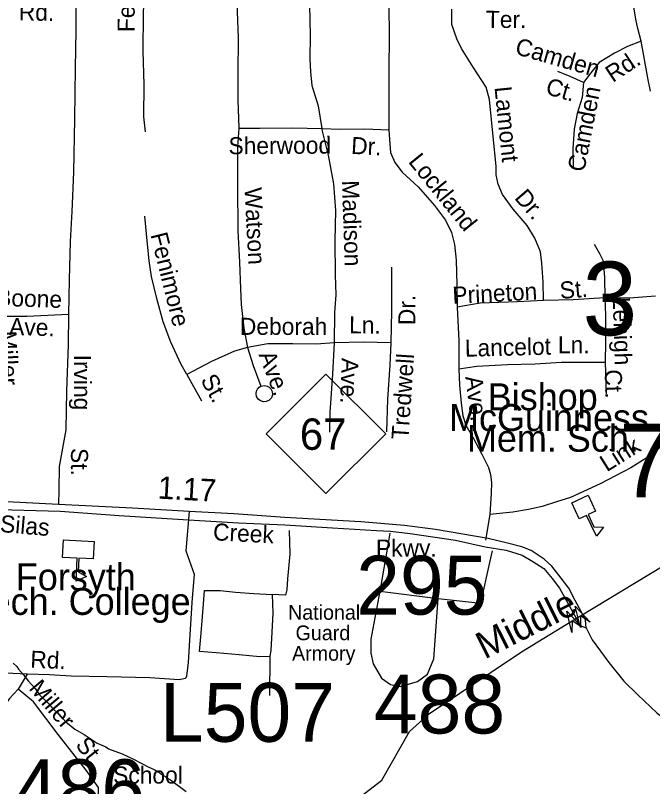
# Model space of a CAD drawing. Extents: x 1547597 to 1699558, y 810033 to 920809.
# Drawn here: x 1623759 to 1627311, y 845229 to 849529 of the extents above; entities that cross this region are included whole.
import ezdxf

# ---------------------------------------------------------------- set-up
doc = ezdxf.new("R2010")
doc.units = 0
for name, color, linetype in [('Exist Cultural Armory Label', 7, 'Continuous'), ('Exist Cultural Educational Facility College or University CELL', 7, 'Continuous'), ('Exist Cultural Educational Facility College or University Label', 7, 'Continuous'), ('Exist Cultural Educational Facility High CELL', 7, 'Continuous'), ('Exist Cultural Educational Facility High Label', 7, 'Continuous'), ('Exist Hydrographic Creek Single Shore', 7, 'Continuous'), ('Exist Hydrographic Creek Single Shore Label', 7, 'Continuous'), ('Exist Hydrographic Misc Water Feature', 7, 'Continuous'), ('Exist Road Non-System Type 51', 7, 'Continuous'), ('Exist Road Non-System Type 51 Label', 7, 'Continuous'), ('Exist Road Primary Interstate Structure Cantilever Sign Number Label', 7, 'Continuous'), ('Exist Road Primary NC Divided Attributed', 7, 'Continuous'), ('Exist Road Primary NC Label', 7, 'Continuous'), ('Exist Road Primary NC Service Mileage Hundredths English Label', 7, 'Continuous'), ('Exist Road Primary NC Shield CELL', 7, 'Continuous'), ('Exist Road Primary NC Shield Number Label', 7, 'Continuous'), ('Exist Road Primary NC UnDivided 4 Lane Attributed', 7, 'Continuous'), ('Exist Road Secondary Structure Standard Bridge Attributed CELL', 7, 'Continuous'), ('Exist Road Secondary Structure Standard Bridge Number Label', 7, 'Continuous')]:
    doc.layers.add(name, color=color, linetype=linetype)

msp = doc.modelspace()

# ---------------------------------------------------------------- linework, layer by layer
at = {"layer": 'Exist Cultural Educational Facility College or University CELL'}
msp.add_lwpolyline([(1624197.9, 846596.8), (1624193.5, 846498.9), (1624112.6, 846502.5), (1624109.3, 846427.5), (1624155.2, 846401.2), (1624097.3, 846374.6), (1624103, 846502.9), (1624022, 846506.5), (1624026.4, 846604.4)], close=True, dxfattribs=at)
at = {"layer": 'Exist Cultural Educational Facility High CELL'}
msp.add_lwpolyline([(1626952.6, 846853.8), (1626994, 846765.1), (1626952.3, 846745.6), (1626984.1, 846677.6), (1627037, 846675.5), (1626998, 846625.1), (1626943.6, 846741.6), (1626901.9, 846722.1), (1626860.5, 846810.8)], close=True, dxfattribs=at)
at = {"layer": 'Exist Hydrographic Creek Single Shore'}
for points in [[(1626579.8, 845980.8), (1626862.2, 846153.4), (1626909, 846181.6), (1627369.8, 846460.4), (1627645.6, 846730.9)], [(1625489.8, 844883.5), (1625567.8, 845085.4), (1625802.8, 845264.5), (1625956.8, 845537.1), (1626066.8, 845636.6), (1626579.8, 845980.8)]]:
    msp.add_lwpolyline(points, dxfattribs=at)
at = {"layer": 'Exist Hydrographic Misc Water Feature'}
msp.add_lwpolyline([(1623747.4, 845917.9), (1623767.1, 845899.6), (1623776.9, 845883.4), (1623804.5, 845853.1), (1623829.9, 845818.7), (1623869.4, 845776.2), (1623892.9, 845741.8), (1623942.2, 845695.2), (1623959.9, 845672.9), (1624007.3, 845628.3), (1624040.7, 845589.8), (1624090.1, 845549.1), (1624141.7, 845520.4), (1624215, 845471.4), (1624262.7, 845450.8), (1624278.6, 845440.6), (1624354.1, 845411.5), (1624417.7, 845382.6), (1624503, 845337.4), (1624532.8, 845325), (1624552.6, 845310.8), (1624560.5, 845308.6), (1624568.4, 845300.5), (1624592.3, 845288.2), (1624600.2, 845280.1), (1624624, 845267.7), (1624711, 845202.5)], dxfattribs=at)
at = {"layer": 'Exist Road Non-System Type 51'}
for p, q in [((1627046.5, 847596.7), (1627051.9, 847418.7)), ((1624715.6, 847527.3), (1624797.3, 847380.2)), ((1626404, 846746.9), (1626380.8, 846602.8)), ((1625285, 846657.5), (1625287.4, 846589.8)), ((1625845.9, 846642.5), (1625834.6, 846575.4)), ((1625834.6, 846575.4), (1625791.2, 846318.2)), ((1626404.1, 846478.2), (1626418.9, 846544.3)), ((1626353.1, 846251.4), (1626404.1, 846478.2)), ((1625791.2, 846318.2), (1626116.5, 846277.4)), ((1626116.5, 846277.4), (1626353.1, 846251.4)), ((1625177.2, 845954.9), (1625174.9, 845736.5)), ((1623825, 845855.3), (1623773.9, 845772))]:
    msp.add_line(p, q, dxfattribs=at)
for points in [[(1624977.3, 850355.2), (1624981.9, 850120.9), (1624992.7, 849850), (1624993, 849600.1), (1625001.8, 849404), (1624999, 849204.1), (1624998.6, 849058.2), (1625004.2, 848900.2)], [(1624484.5, 848880), (1624475.6, 848964.2), (1624476.5, 849144.1), (1624471.2, 849330.1), (1624472.5, 849537.8), (1624478.7, 849687.7), (1624477, 849829.7), (1624473.4, 849999.6), (1624463.9, 850198.2)], [(1627247.9, 849385.9), (1627229, 849456.4), (1627219.9, 849499.8), (1627202.2, 849597.2), (1627212.4, 849676.8), (1627206.4, 849676.9)], [(1624095.6, 849595.5), (1624095.4, 849447.6), (1624092.1, 849235.7), (1624088, 848951.9), (1624083.4, 848656.2), (1624074.1, 848436.4), (1624063.5, 848268.8), (1624058.4, 848055), (1624055.2, 847861.1)], [(1625398.3, 849586), (1625401.8, 849420.1), (1625399.8, 849286.2), (1625404.6, 849214.1), (1625411.5, 849138.1), (1625447.8, 849025.7), (1625467.8, 848899.4)], [(1625841.5, 849573.8), (1625843.3, 849423.9), (1625840.1, 849216.3), (1625841.3, 849032.3), (1625841.1, 848890.5)], [(1626704, 847939.4), (1626701.5, 848043.5), (1626693.3, 848147.6), (1626686.1, 848211.6), (1626655.5, 848288), (1626612.5, 848358.7), (1626533.9, 848449.8), (1626475.3, 848530.6), (1626450.1, 848589), (1626438.9, 848641), (1626439.7, 848687), (1626401.4, 849061.4), (1626384.4, 849129.6), (1626310.2, 849240.6), (1626245.9, 849345.5), (1626220.8, 849397.9), (1626192, 849478.3), (1626191.3, 849564.1)], [(1627247.9, 849385.9), (1627172.1, 849356.3), (1627099.6, 849319.2), (1627012.9, 849266), (1626966.9, 849209.4), (1626926.2, 849154.5)], [(1627299.5, 849106.6), (1627287.1, 849170.4), (1627247.9, 849385.9)], [(1626926.2, 849154.5), (1626852.8, 849188.5), (1626782.8, 849216.4)], [(1626926.2, 849154.5), (1626919.1, 849071.7), (1626891.7, 848982.2), (1626874.5, 848894.5), (1626866.7, 848784.6), (1626869.1, 848678.7)], [(1625004.2, 848900.2), (1624996.7, 848796.5), (1624997.3, 848580.6), (1624999.6, 848328.6), (1625008.9, 848152.7), (1625014.7, 848004.7), (1625017.3, 847916.6), (1625033.2, 847786.4), (1625053.7, 847678.4)], [(1625004.2, 848900.2), (1625122.1, 848900.5), (1625304, 848901.8), (1625467.8, 848899.4)], [(1625467.8, 848899.4), (1625569.6, 848896), (1625707.5, 848897.8), (1625841.1, 848890.5)], [(1625537.6, 847703.2), (1625540.1, 847873), (1625547.7, 847970.7), (1625543.3, 848082.7), (1625542.2, 848272.6), (1625544.8, 848442.4), (1625535, 848590.5), (1625505.5, 848751), (1625467.8, 848899.4)], [(1625841.1, 848890.5), (1625845.9, 848812.3), (1625851.1, 848764.4), (1625874.4, 848710.1), (1625915.5, 848655.4), (1626004.1, 848574.2), (1626096.4, 848468.9), (1626157.2, 848388), (1626190.1, 848319.7), (1626207.1, 848251.3), (1626215.8, 848165.3), (1626219.8, 848027.3), (1626221.8, 847903.4)], [(1624715.6, 847527.3), (1624682.5, 847583.8), (1624626.4, 847706.6), (1624582.3, 847821.2), (1624548.3, 847951.8), (1624518.2, 848074), (1624505.5, 848160.1), (1624489.8, 848312.3), (1624481.2, 848410.4)], [(1626986.5, 848253.1), (1627015.7, 848202.7), (1627035.1, 848160.5), (1627043.6, 848068.4), (1627045.9, 847954.5)], [(1625855.8, 848126.1), (1625856.4, 848040.1), (1625856, 847880.2), (1625851.2, 847704.4)], [(1627045.9, 847954.5), (1626868, 847943.1), (1626704, 847939.4)], [(1627327.9, 847964.2), (1627181.8, 847952.4), (1627045.9, 847954.5)], [(1627045.9, 847954.5), (1627048.6, 847858.4), (1627048.1, 847708.5), (1627046.5, 847596.7)], [(1626704, 847939.4), (1626558, 847931.8), (1626350.1, 847924.8), (1626221.8, 847903.4)], [(1626221.8, 847903.4), (1626230.8, 847715.3), (1626230.5, 847559.4)], [(1624055.2, 847861.1), (1623822.1, 847850.9), (1623611, 847850.9)], [(1624055.2, 847861.1), (1624052.8, 847693.3), (1624044.8, 847435.5), (1624039.6, 847217.7), (1624002.5, 847014.9), (1624001, 846884), (1623998.7, 846803.1)], [(1625537.6, 847703.2), (1625435.6, 847696.6), (1625305.6, 847698.5), (1625165.7, 847698.7), (1625053.7, 847678.4)], [(1625511.9, 847205.8), (1625513.8, 847315.6), (1625528.9, 847529.2), (1625537.6, 847703.2)], [(1625851.2, 847704.4), (1625699.4, 847706.7), (1625537.6, 847703.2)], [(1625851.2, 847704.4), (1625847.3, 847578.6), (1625834.4, 847388.8), (1625827.7, 847207)], [(1625053.7, 847678.4), (1624981.4, 847657.4), (1624852.6, 847599.4), (1624715.6, 847527.3)], [(1625053.7, 847678.4), (1625084, 847577.9), (1625128.3, 847461.3)], [(1626230.5, 847559.4), (1626330.8, 847573.4), (1626502.9, 847582.7), (1626656.7, 847586.4), (1626802.7, 847596.2), (1626942.6, 847596.2), (1627046.5, 847596.7)], [(1626230.5, 847559.4), (1626235.2, 847467.5), (1626243.6, 847367.5), (1626252.6, 847297.2), (1626269.7, 847245.1), (1626312.3, 847171.1), (1626357.4, 847087.2), (1626377.6, 847045.2), (1626396.2, 847009.5), (1626408.6, 846969.1), (1626413.3, 846924), (1626411.7, 846868.1), (1626404, 846746.9)], [(1625128.3, 847461.3), (1625147, 847465.1), (1625162.5, 847462.6), (1625174.4, 847456.2), (1625183.8, 847447.2), (1625190.9, 847432), (1625192.2, 847414.2), (1625186.4, 847396.7), (1625172.9, 847382.6), (1625158, 847375.9), (1625142.9, 847374.4), (1625125, 847379.5), (1625112.8, 847389.6), (1625103.8, 847405.4), (1625101.3, 847421.3), (1625103.9, 847434.2), (1625109.4, 847446.1), (1625118.8, 847456.3), (1625128.3, 847461.3)], [(1627501.7, 847310.1), (1627468.7, 847242.5), (1627407.6, 847167.5), (1627310.4, 847083.1), (1627189.4, 847006.9), (1627018.3, 846917.5), (1626853.3, 846842), (1626774.9, 846817.2), (1626696.5, 846790.4), (1626620.3, 846773.5), (1626533, 846759.7), (1626404, 846746.9)], [(1624728.7, 846763), (1624709.8, 846544.4), (1624756.6, 846412.9), (1624742.2, 846255.3), (1624731.6, 846075.4), (1624723.1, 845921.7), (1624713.9, 845845.8), (1624707.8, 845831.9), (1624671.7, 845824.5), (1624508, 845835), (1624270.4, 845840.6), (1624070.8, 845845.5), (1623949.1, 845853.3), (1623825, 845855.3)], [(1625287.4, 846589.8), (1625289.8, 846524.9), (1625275.6, 846387.1), (1625272.8, 846327.2), (1625264.4, 846297.3), (1625190.4, 846300.4)], [(1625177.2, 845954.9), (1625121.1, 845953.6), (1625007.5, 845963.3), (1624877.8, 845975.4), (1624785.9, 845982.6), (1624793.2, 846064.5), (1624800.6, 846154.4), (1624808.1, 846248.1), (1624813.2, 846322.1), (1624901.1, 846322.7), (1624986.8, 846313.6), (1625088.6, 846305.9), (1625190.4, 846300.4)], [(1625791.2, 846318.2), (1625741, 846052.3), (1625741.1, 845972.8), (1625754.5, 845913.1), (1625800.8, 845833.6), (1625849.6, 845799.3), (1625906.3, 845787.3), (1626000.5, 845815), (1626057.1, 845855.9), (1626091.7, 845940.9), (1626116.5, 846277.4)], [(1625190.4, 846300.4), (1625194.9, 846196.5), (1625186.6, 846054.8), (1625183.7, 845990.8), (1625177.2, 845954.9)], [(1623825, 845855.3), (1623705.3, 845861.1), (1623649.6, 845865.8), (1623591.3, 845856.8)], [(1623400.4, 845134.2), (1623431.9, 845073.5), (1623419.8, 844986.2), (1623448.9, 844918.3), (1623514.3, 844872.2), (1623674.3, 844850.4), (1623907, 844867.4), (1624100.9, 844903.7), (1624197.9, 844928), (1624234.2, 844998.3), (1624224.5, 845100.2), (1624222.1, 845223.9), (1624154.2, 845321), (1623996.7, 845519.9), (1623860.9, 845701.8), (1623773.9, 845772)], [(1623773.9, 845772), (1623725.3, 845720.8), (1623694.5, 845675.2), (1623657.4, 845589.9), (1623625.4, 845462.5), (1623581.3, 845323.1), (1623548.2, 845249.7), (1623519.6, 845212.1), (1623481.2, 845182.9), (1623415, 845161.8)]]:
    msp.add_lwpolyline(points, dxfattribs=at)
at = {"layer": 'Exist Road Primary NC Divided Attributed'}
for points in [[(1626914.7, 846202.4), (1626880.3, 846267.8), (1626845.1, 846335.1), (1626802.3, 846391.7), (1626750.4, 846457.5), (1626706.1, 846497.2), (1626634.9, 846545.5), (1626582.7, 846565.9), (1626501.8, 846587.1), (1626394.3, 846613.6), (1626101.6, 846663.5), (1625928.4, 846685.8), (1625684.1, 846706.3), (1625262, 846730.5), (1624976.8, 846749.4), (1624728.7, 846763), (1624411.7, 846781.9), (1623998.7, 846803.1), (1623600.9, 846822.4), (1623030.5, 846807.2), (1622501, 846804.2)], [(1622503.3, 846760.3), (1622784.7, 846761.1), (1622891.3, 846763), (1623092.5, 846767.9), (1623603.1, 846777), (1624009.3, 846764.9), (1624336.9, 846741.8), (1624724.9, 846716.8), (1625003.3, 846700.2), (1625262, 846688.9), (1625526, 846673), (1625772.6, 846657.8), (1625850.5, 846654.1), (1625959.4, 846640.8), (1626212.8, 846603.8), (1626377.7, 846566.7), (1626495.7, 846547), (1626585, 846519), (1626643.4, 846485), (1626704.6, 846445.2), (1626751.9, 846390.2), (1626793.2, 846335.1), (1626876.2, 846184.7)], [(1626876.2, 846184.7), (1626907.2, 846128), (1626940.5, 846115.1)], [(1626940.5, 846115.1), (1626936.7, 846156.7), (1626914.7, 846202.4)]]:
    msp.add_lwpolyline(points, dxfattribs=at)
at = {"layer": 'Exist Road Primary NC Shield CELL'}
msp.add_lwpolyline([(1625157.6, 847196.9), (1625490.6, 847529.9), (1625823.6, 847196.9), (1625490.6, 846863.9)], close=True, dxfattribs=at)
at = {"layer": 'Exist Road Primary NC UnDivided 4 Lane Attributed'}
msp.add_lwpolyline([(1626940.5, 846115.1), (1626973.8, 846048.5), (1627067.6, 845921.8), (1627151.5, 845817.8), (1627228.7, 845740.7), (1627334.6, 845640.8), (1627493.4, 845512.2), (1627636.4, 845412.4), (1627708.7, 845379.5), (1627794.6, 845350.1), (1627934.1, 845330.2), (1627984, 845323), (1628100.8, 845313.6)], dxfattribs=at)
at = {"layer": 'Exist Road Secondary Structure Standard Bridge Attributed CELL'}
for points in [[(1626908.7, 846116.6), (1626879.6, 846235), (1626964, 846147.1), (1626909, 846181.6)], [(1626862, 846088.4), (1626832.9, 846206.8), (1626917.3, 846118.9), (1626862.2, 846153.4)]]:
    msp.add_lwpolyline(points, close=True, dxfattribs=at)

# ---------------------------------------------------------------- texts
at = {"layer": 'Exist Cultural Armory Label'}
for s, p in [('National', (1625279, 846159.8)), ('Guard', (1625321, 846045.6)), ('Armory', (1625301.3, 845931.4))]:
    msp.add_text(s, height=82.02, dxfattribs=at).set_placement(p)
at = {"layer": 'Exist Cultural Educational Facility College or University Label'}
for s, p in [('Forsyth', (1623761.4, 846323.7)), ('Tech. College', (1623498.5, 846186.7))]:
    msp.add_text(s, height=150, dxfattribs=at).set_placement(p)
at = {"layer": 'Exist Cultural Educational Facility High Label'}
for s, p in [('Bishop', (1626392.3, 847327.9)), ('McGuinness', (1626176.4, 847212.1)), ('Mem. Sch.', (1626276.3, 847096.4))]:
    msp.add_text(s, height=150, dxfattribs=at).set_placement(p)
at = {"layer": 'Exist Hydrographic Creek Single Shore Label'}
msp.add_text('Middle', height=150, rotation=26.6517, dxfattribs=at).set_placement((1626375.5, 845937.4))
at = {"layer": 'Exist Road Non-System Type 51 Label'}
for s, rotation, p in [('Fenmore', 89.6693, (1624423.6, 849436.1)), ('Rd.', 359.169, (1623777.3, 849501.4)), ('Ter.', 359.6289, (1626381.9, 849460.2)), ('Camden', 343.9726, (1626539.1, 849315.6)), ('Rd.', 33.6369, (1627089.3, 849152.4)), ('Ct.', 343.9726, (1626709.5, 849092.5)), ('Lamont', 275.8302, (1626429.9, 849129.2)), ('Camden', 78.9132, (1626929.8, 848652.5)), ('Sherwood', 0.4123, (1624947.4, 848755)), ('Dr.', 356.8651, (1625629, 848757.7)), ('Lockland', 308.9573, (1625945.7, 848712.8)), ('Madison', 271.9385, (1625579.4, 848608.6)), ('Watson', 273.0068, (1625036.3, 848567.5)), ('Dr.', 310.8035, (1626537.1, 848509.8)), ('Fenimore', 283.844, (1624511.4, 848307.1)), ('Prineton', 2.9965, (1626197.7, 847920.7)), ('St.', 4.634, (1626797.5, 847948.3)), ('Boone', 358.145, (1623650.8, 847910.1)), ('Dr.', 89.8413, (1625988.7, 847802.2)), ('Lehigh', 271.7355, (1627089.3, 847958.5)), ('Ave.', 358.145, (1623723.2, 847748.4)), ('Deborah', 359.9032, (1625010.5, 847748.2)), ('Ln.', 359.1396, (1625618.9, 847757.1)), ('Miller', 272.0938, (1623669.7, 847769.3)), ('Lancelot', 1.3727, (1626265.7, 847626.3)), ('Ln.', 359.9852, (1626783.8, 847645.5)), ('Irving', 269.9641, (1624085.8, 847638)), ('Ave.', 290.7918, (1625114, 847637.6)), ('Ave.', 268.1499, (1625578, 847620.2)), ('Tredwell', 86.1265, (1625949.9, 847161.7)), ('St.', 299.0297, (1624788.8, 847496.8)), ('Ave.', 277.0549, (1626267.1, 847514.1)), ('Ct.', 271.7355, (1627044.4, 847554.4)), ('Link', 32.1943, (1627056.2, 846981.2)), ('St.', 269.916, (1624069.1, 847117.3)), ('Rd.', 357.6309, (1623840.8, 845892.4)), ('Miller', 310.243, (1623830.5, 845775.5)), ('St.', 308.5065, (1624089.7, 845460.1))]:
    msp.add_text(s, height=95, rotation=rotation, dxfattribs=at).set_placement(p)
msp.add_text('School', height=95, dxfattribs=at).set_placement((1624304, 845246.3))
at = {"layer": 'Exist Road Primary Interstate Structure Cantilever Sign Number Label'}
msp.add_text('L507', height=328.08, dxfattribs=at).set_placement((1624564.9, 845479.2))
at = {"layer": 'Exist Road Primary NC Label'}
for s, rotation, p in [('Silas', 355.2051, (1623671, 846649.3)), ('Creek', 357.09, (1624859.2, 846603.1)), ('Pkwy.', 0.0647, (1625769.2, 846511.9))]:
    msp.add_text(s, height=95, rotation=rotation, dxfattribs=at).set_placement(p)
at = {"layer": 'Exist Road Primary NC Service Mileage Hundredths English Label'}
msp.add_text('1.17', height=125, rotation=356.8589, dxfattribs=at).set_placement((1624550.3, 846835.4))
at = {"layer": 'Exist Road Primary NC Shield Number Label'}
msp.add_text('67', height=175, dxfattribs=at).set_placement((1625344.7, 847107.2))
at = {"layer": 'Exist Road Secondary Structure Standard Bridge Number Label'}
for s, height, p in [('3', 410.1, (1626920.8, 847746.2)), ('7', 410.1, (1627124.4, 846843.1)), ('295', 328.08, (1625659.1, 846188.3)), ('488', 328.08, (1625757.5, 845525.5)), ('486', 328.08, (1623750, 845053.1))]:
    msp.add_text(s, height=height, dxfattribs=at).set_placement(p)

doc.saveas('drawing.dxf')
